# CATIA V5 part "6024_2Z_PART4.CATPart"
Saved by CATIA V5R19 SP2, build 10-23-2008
Part number: 6024_2Z_PART4
Bounding box of the stored display mesh (mm): x 26.075 to 26.845, y -82.411 to 82.411, z -82.48 to 82.48
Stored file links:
  G:\EU_thinkMotion\CFAO_2010\MMS_groupe2\MMS_groupe2\OK\nrosalie\nrosalie_cfao_support_d_arme_legere_final\6024_2Z_PART4.CATPart
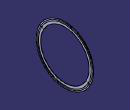
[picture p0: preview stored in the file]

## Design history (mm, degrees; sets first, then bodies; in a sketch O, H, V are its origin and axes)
Set1
  Point1: (0, 0, 0)
  Point2: (1, 0, 0)
  Point3: (0, 1, 0)
  Plane1: type 3Points, Element1 Point1, Element2 Point2, Element3 Point3
Body1 (main body)
  Sketch1 on Plane1, origin (0, 0, 0), H (1, 0, 0), V (0, 1, 0)
    point P1 (26.075, 79.2158)
    point P2 (26.075, 76)
    line L1 (26.075, 79.2158) -> (26.075, 76)
    point P3 (26.075, 76)
    point P4 (26.46, 69.5)
    line L2 (26.075, 76) -> (26.46, 69.5)
    point P5 (26.46, 69.5)
    point P6 (26.845, 69.5)
    line L3 (26.46, 69.5) -> (26.845, 69.5)
    point P7 (26.845, 69.5)
    point P8 (26.845, 76)
    line L4 (26.845, 69.5) -> (26.845, 76)
    point P9 (26.845, 76)
    point P10 (26.6525, 79.25)
    line L5 (26.845, 76) -> (26.6525, 79.25)
    point P11 (26.6525, 79.25)
    point P12 (26.845, 82.5)
    line L6 (26.6525, 79.25) -> (26.845, 82.5)
    point P13 (26.845, 82.5)
    point P14 (26.46, 82.5)
    line L7 (26.845, 82.5) -> (26.46, 82.5)
    point P15 (26.46, 82.5)
    point P16 (26.075, 79.2158)
    line L8 (26.46, 82.5) -> (26.075, 79.2158)
    point P17 (50, 0)
    point P18 (-50, 0)
    axis line L9 (50, 0) -> (-50, 0)
    point P19 (26.075, 79.2158)
    point P20 (26.075, 76)
    point P21 (26.075, 76)
    point P22 (26.46, 69.5)
    point P23 (26.46, 69.5)
    point P24 (26.845, 69.5)
    point P25 (26.845, 69.5)
    point P26 (26.845, 76)
    point P27 (26.845, 76)
    point P28 (26.6525, 79.25)
    point P29 (26.6525, 79.25)
    point P30 (26.845, 82.5)
    point P31 (26.845, 82.5)
    point P32 (26.46, 82.5)
    point P33 (26.46, 82.5)
    point P34 (26.075, 79.2158)
    coincidence: P19 P34, P20 P21, P22 P23, P24 P25, P26 P27, P28 P29, P30 P31, P32 P33
  Shaft1: profile Sketch1, axis Sketch1.L9, angle 360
